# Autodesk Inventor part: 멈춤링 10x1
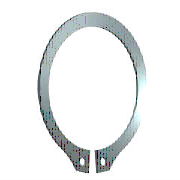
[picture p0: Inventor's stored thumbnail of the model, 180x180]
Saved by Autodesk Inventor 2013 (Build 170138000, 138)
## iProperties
IsCustomPart: 0
Created: 2015-11
Part Number: 멈춤링 10x1
Material: 스테인리스강
Description: 리테이닝 링(C형)
Document SubType Name: Modeling
Standard: KS B 1336
Designer: mdu
Standards Organization: KS
Language: ko-KR
Size Designation: 10 x 1
Categories: <MemberInstance><Categories><Category DisplayName="샤프트 부품" InternalName="7f7aeb1f-a693-4053-b835-cee3144e0d98" Mnemonic="SHFT"><Category DisplayName="써클립" Inter
Density: 1 g/cm^3
Author: mdu
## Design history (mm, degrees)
sketch "스케치1"
  geometry: L1 (-6, 0)-(6, 0) reference; L2 (0, 20.189)-(0, -80.536) reference; L3 (-48.09, 0)-(48.09, 0) reference; L4 (-0.3, -9.791)-(-0.3, -12.791); L5 (-0.3, -6.54)-(-0.3, -13.29); L6 (-2.795, 1.6)-(3.672, 1.6); L7 (0.3, -6.54)-(0.3, -13.29); L8 (0.3, -9.791)-(0.3, -12.791); C1 r 0.6 at (-1.2, -11.486); C2 r 0.6 at (1.2, -11.486); A1 r 4.8 centre (0, -5) between (0.3, -9.791) and (-0.3, -9.791); A2 r 6.2 centre (0, -4.6) between (2.988, -10.033) and (-2.988, -10.033); A3 r 7.796 centre (0, -5) between (-1.418, -12.666) and (-0.3, -12.791); A4 r 1.2 centre (-1.2, -11.486) between (-2.383, -11.285) and (-1.418, -12.666); A5 r 1.2 centre (-3.566, -11.084) between (-2.383, -11.285) and (-2.988, -10.033); A6 r 1.2 centre (3.566, -11.084) between (2.988, -10.033) and (2.383, -11.285); A7 r 1.2 centre (1.2, -11.486) between (1.418, -12.666) and (2.383, -11.285); A8 r 7.796 centre (0, -5) between (0.3, -12.791) and (1.418, -12.666)
  constraints: 16 point on circle, 12 end point, 10 centre point, 9 symmetric about line, 5 point on line, 4 tangent, 3 coincident, 2 horizontal, 1 perpendicular, 1 vertical, 5 other
  dimensions: "d0" = 9.6 diameter of A1 (= ND); "d1" = 3 distance of L4.end L4.start (= SRB2); "d6" = 0.3 distance between parallel lines of L2 L5 (= 0.25 x SD5); "d7" = 1.6 distance between parallel lines of L6 L3 (= SRB1); "d8" = 0.4 distance of A1.centre A2.centre (= 0.25 x SRB1); "d9" = 1.2 radius of A4 (= SD5); "d10" = 1.2 radius of A5 (= SD5); "d11" = 0.9 distance from line of L4 A4.centre (= 0.75 x SD5); "d12" = 1.2 diameter of C1 (= SD5); "d13" = 1.2 diameter of C2 (= SD5); "d14" = 5 distance from line of A1.centre L1 (= 0.5 x WD)
extrude "본체" new body sketch "스케치1" distance "d2" = 1 (= SD); taper "d3" = 0 deg
workaxis "Work Axis1"
workplane "Work Plane1"
body "Solid1"
other parameters: "SD" = 1 [user parameter; used in 1 equation term], "SRB1" = 1.6 [user parameter; used in 2 equation terms], "ND" = 9.6 [user parameter; used in 1 equation term], "SRB2" = 3 [user parameter; used in 1 equation term], "SD5" = 1.2 [user parameter; used in 6 equation terms], "d15" = 0, "d16" = 0, "d17" = 0, "d41" = 0, "d42" = 0, "SD3" = 9.3 [user parameter], "WDMAX" = 11 [user parameter]
